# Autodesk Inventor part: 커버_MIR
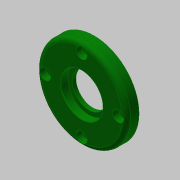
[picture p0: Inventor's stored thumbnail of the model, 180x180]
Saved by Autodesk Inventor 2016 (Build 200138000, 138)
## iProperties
Created: 2019-09
Part Number: 커버_MIR
Material: 알루미늄 6061
Document SubType Name: Modeling
Designer: Administrator
Density: 2.71 g/cm^3
Appearance: 알루미늄 - 평지
Author: mduedu
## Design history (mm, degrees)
derived "커버.ipt"
  sketch "스케치1"
    geometry: C1 r 32 at (0, 0) reference; 1 further point
    dimensions: "d0" = 10 dimension on point (0, 0) C1.centre C1
  sketch "스케치2"
    geometry: C1 r 21 at (0, 0) reference; 1 further point
    dimensions: "d0" = 10 dimension on point (0, 0) C1.centre C1
  sketch "스케치3"
    geometry: 3 further points
    constraints: 1 vertical alignment
    dimensions: "d0" = 10 dimension on point (0, 0) point (0, 0) point (0, 26)
feature "솔리드1::커버.ipt"
tag "피쳐 태그1"
node "솔리드1"
